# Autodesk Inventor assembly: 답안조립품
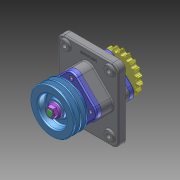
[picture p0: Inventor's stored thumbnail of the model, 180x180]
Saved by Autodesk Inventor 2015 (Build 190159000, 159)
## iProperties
Created: 2026-07
Part Number: 답안조립품
Document SubType Name: Assembly
Designer: USER
Author: USER
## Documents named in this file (12)
- C:\Users\USER\Desktop\760705V1009\답안조립품.iam
- C:\Users\USER\Desktop\760705V1009\본체.ipt
- C:\Users\USER\Desktop\760705V1009\가져온 구성요소\6각 구멍붙이 볼트 M6x16\6각 구멍붙이 볼트 M6x16.ipt
- C:\Users\USER\Desktop\760705V1009\가져온 구성요소\6각 플랜지 너트 M16\6각 플랜지 너트 M16.ipt
- C:\Users\USER\Desktop\760705V1009\가져온 구성요소\V-벨트풀리\V-벨트풀리.ipt
- C:\Users\USER\Desktop\760705V1009\가져온 구성요소\깊은 홈 볼 베어링 6206\깊은 홈 볼 베어링 6206.ipt
- C:\Users\USER\Desktop\760705V1009\가져온 구성요소\오일 실 30 45 8\오일 실 30 45 8.ipt
- C:\Users\USER\Desktop\760705V1009\가져온 구성요소\체인 스프로킷\체인 스프로킷.ipt
- C:\Users\USER\Desktop\760705V1009\가져온 구성요소\축\축.ipt
- C:\Users\USER\Desktop\760705V1009\가져온 구성요소\칼라\칼라.ipt
- C:\Users\USER\Desktop\760705V1009\가져온 구성요소\커버\커버.ipt
- C:\Users\USER\Desktop\760705V1009\가져온 구성요소\평행 키 6x6x20\평행 키 6x6x20.ipt
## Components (11 placed, 3 different names)
1. 6각 구멍붙이 볼트 M6x16:1
2. 6각 플랜지 너트 M16:1
3. V-벨트풀리:1
4. 6각 구멍붙이 볼트 M6x16:2
5. 6각 구멍붙이 볼트 M6x16:3
6. 6각 구멍붙이 볼트 M6x16:5
7. 6각 구멍붙이 볼트 M6x16:6
8. 6각 구멍붙이 볼트 M6x16:7
9. 6각 구멍붙이 볼트 M6x16:8
10. 6각 구멍붙이 볼트 M6x16:9
11. 6각 플랜지 너트 M16:2
